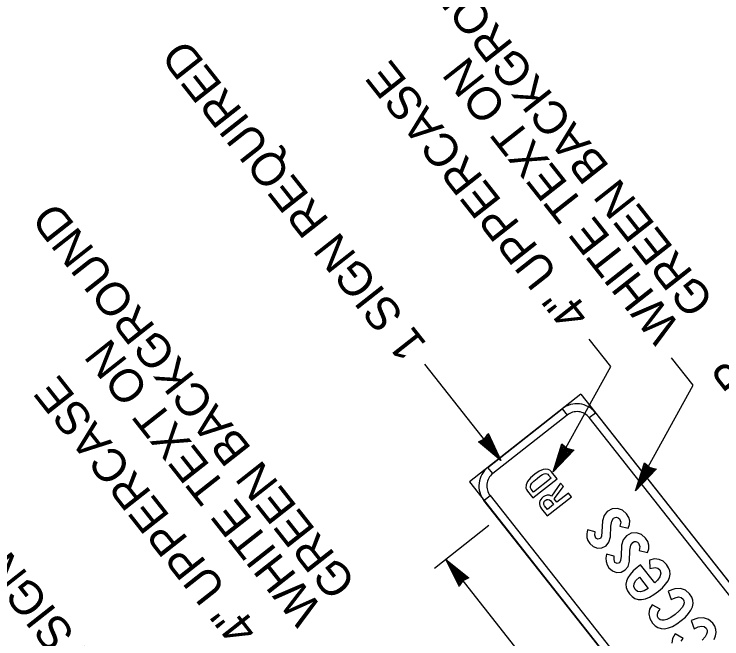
# Model space of a CAD drawing. Extents: x 672126 to 673696, y 1673540 to 1674900.
# Drawn here: x 672217.5 to 672307.3, y 1674682.5 to 1674761.8 of the extents above; entities that cross this region are included whole.
import ezdxf

# ---------------------------------------------------------------- set-up
doc = ezdxf.new("R2010")
doc.units = 0
doc.layers.add('C-ANNO-SYMB', color=7, linetype='Continuous')
doc.layers.add('Level 1', color=7, linetype='Continuous')

msp = doc.modelspace()

# ---------------------------------------------------------------- linework, layer by layer
at = {"layer": 'C-ANNO-SYMB'}
for p, q in [((672289.398, 1674713.6), (672275.262, 1674702.456)), ((672289.398, 1674713.6), (672333.973, 1674657.057)), ((672287.042, 1674711.743), (672287.661, 1674710.957)), ((672290.47, 1674710.625), (672291.255, 1674711.244)), ((672278.237, 1674703.528), (672277.618, 1674704.313)), ((672275.262, 1674702.456), (672319.838, 1674645.914)), ((672277.12, 1674700.1), (672277.905, 1674700.719))]:
    msp.add_line(p, q, dxfattribs=at)
for points in [[(672287.661, 1674710.957), (672278.237, 1674703.528), (672277.618, 1674704.313), (672287.042, 1674711.743), (672287.661, 1674710.957), (672287.661, 1674710.957)], [(672331.331, 1674658.794), (672290.47, 1674710.625), (672291.255, 1674711.244), (672332.116, 1674659.413), (672331.331, 1674658.794), (672331.331, 1674658.794)], [(672277.905, 1674700.719), (672318.766, 1674648.889), (672317.98, 1674648.27), (672277.12, 1674700.1), (672277.905, 1674700.719), (672277.905, 1674700.719)], [(672295.431, 1674696.575), (672295.593, 1674697.048), (672295.606, 1674697.514), (672295.476, 1674697.968), (672295.198, 1674698.414), (672294.678, 1674698.876), (672294.042, 1674699.085), (672293.377, 1674699.029), (672292.757, 1674698.696), (672292.36, 1674698.206), (672292.139, 1674697.505), (672292.076, 1674696.133), (672292.026, 1674695.564), (672291.886, 1674695.279), (672291.582, 1674695.19), (672291.31, 1674695.33), (672291.186, 1674695.704), (672291.212, 1674696.119), (672290.23, 1674696.362), (672290.154, 1674695.877), (672290.178, 1674695.427), (672290.307, 1674695.014), (672290.535, 1674694.64), (672290.976, 1674694.25), (672291.518, 1674694.064), (672292.088, 1674694.098), (672292.604, 1674694.368), (672292.965, 1674694.826), (672293.15, 1674695.501), (672293.208, 1674696.867), (672293.324, 1674697.494), (672293.568, 1674697.867), (672293.747, 1674697.958), (672293.95, 1674697.972), (672294.148, 1674697.907), (672294.302, 1674697.769), (672294.475, 1674697.338), (672294.371, 1674696.829)], [(672297.858, 1674693.496), (672298.02, 1674693.97), (672298.033, 1674694.435), (672297.903, 1674694.89), (672297.625, 1674695.336), (672297.105, 1674695.798), (672296.469, 1674696.007), (672295.803, 1674695.951), (672295.184, 1674695.618), (672294.787, 1674695.128), (672294.565, 1674694.426), (672294.503, 1674693.055), (672294.453, 1674692.486), (672294.312, 1674692.201), (672294.009, 1674692.111), (672293.736, 1674692.252), (672293.613, 1674692.626), (672293.639, 1674693.04), (672292.657, 1674693.284), (672292.581, 1674692.798), (672292.605, 1674692.348), (672292.734, 1674691.935), (672292.962, 1674691.561), (672293.403, 1674691.172), (672293.945, 1674690.986), (672294.515, 1674691.02), (672295.031, 1674691.289), (672295.392, 1674691.748), (672295.576, 1674692.423), (672295.635, 1674693.788), (672295.75, 1674694.415), (672295.995, 1674694.788), (672296.174, 1674694.88), (672296.377, 1674694.893), (672296.575, 1674694.829), (672296.729, 1674694.691), (672296.902, 1674694.26), (672296.798, 1674693.75)], [(672300.88, 1674687.534), (672301.372, 1674687.769), (672301.782, 1674687.859), (672302.117, 1674687.799), (672302.374, 1674687.594), (672302.493, 1674687.369), (672302.507, 1674687.118), (672302.426, 1674686.833), (672302.241, 1674686.523), (672301.878, 1674686.083), (672301.382, 1674685.643), (672300.842, 1674685.269), (672300.323, 1674685.019), (672299.981, 1674684.918), (672299.688, 1674684.904), (672299.45, 1674684.977), (672299.26, 1674685.139), (672299.128, 1674685.397), (672299.115, 1674685.674), (672299.224, 1674685.975), (672299.449, 1674686.295), (672298.446, 1674686.868), (672298.133, 1674686.311), (672298.04, 1674685.714), (672298.165, 1674685.112), (672298.498, 1674684.538), (672298.829, 1674684.196), (672299.194, 1674683.966), (672299.597, 1674683.844), (672300.033, 1674683.83), (672300.509, 1674683.924), (672301.018, 1674684.126), (672301.564, 1674684.438), (672302.147, 1674684.857), (672302.669, 1674685.308), (672303.079, 1674685.751), (672303.381, 1674686.188), (672303.567, 1674686.616), (672303.646, 1674687.036), (672303.611, 1674687.449), (672303.466, 1674687.852), (672303.209, 1674688.252), (672302.684, 1674688.724), (672302.056, 1674688.935), (672301.323, 1674688.887), (672300.483, 1674688.583)]]:
    msp.add_lwpolyline(points, close=True, dxfattribs=at)
for points in [[(672286.401, 1674702.865), (672285.693, 1674703.762), (672285.493, 1674703.95), (672285.248, 1674704.057), (672284.962, 1674704.082), (672284.63, 1674704.027), (672284.113, 1674703.816), (672283.587, 1674703.467), (672283.029, 1674702.972), (672282.65, 1674702.509), (672282.452, 1674702.081), (672282.434, 1674701.687), (672282.509, 1674701.498), (672282.657, 1674701.278), (672283.32, 1674700.436), (672286.401, 1674702.865)], [(672285.623, 1674702.937), (672283.396, 1674701.181), (672283.111, 1674701.542), (672283.021, 1674701.712), (672283.006, 1674701.898), (672283.068, 1674702.098), (672283.204, 1674702.312), (672283.456, 1674702.577), (672283.86, 1674702.918), (672284.208, 1674703.193), (672284.524, 1674703.388), (672284.765, 1674703.49), (672284.93, 1674703.516), (672285.077, 1674703.495), (672285.209, 1674703.429), (672285.322, 1674703.319), (672285.623, 1674702.937)], [(672288.209, 1674700.571), (672287.828, 1674701.055), (672286.361, 1674699.898), (672286.037, 1674700.31), (672287.186, 1674701.869), (672286.837, 1674702.311), (672285.672, 1674700.666), (672285.413, 1674700.772), (672285.129, 1674700.784), (672284.867, 1674700.711), (672284.62, 1674700.562), (672284.445, 1674700.403), (672284.31, 1674700.232), (672284.216, 1674700.053), (672284.162, 1674699.863), (672284.151, 1674699.661), (672284.188, 1674699.46), (672284.271, 1674699.26), (672284.401, 1674699.065), (672285.128, 1674698.143), (672288.209, 1674700.571)], [(672285.955, 1674699.578), (672285.17, 1674698.959), (672284.814, 1674699.411), (672284.716, 1674699.591), (672284.696, 1674699.78), (672284.757, 1674699.961), (672284.898, 1674700.116), (672285.089, 1674700.227), (672285.266, 1674700.252), (672285.433, 1674700.192), (672285.587, 1674700.046), (672285.955, 1674699.578)], [(672298.783, 1674689.644), (672296.979, 1674691.932), (672296.555, 1674691.597), (672296.054, 1674691.16), (672295.657, 1674690.728), (672295.372, 1674690.302), (672295.192, 1674689.881), (672295.126, 1674689.464), (672295.165, 1674689.054), (672295.316, 1674688.649), (672295.57, 1674688.253), (672295.903, 1674687.912), (672296.27, 1674687.678), (672296.676, 1674687.554), (672297.113, 1674687.541), (672297.593, 1674687.636), (672298.105, 1674687.84), (672298.654, 1674688.153), (672299.24, 1674688.576), (672299.758, 1674689.024), (672300.166, 1674689.465), (672300.465, 1674689.899), (672300.649, 1674690.325), (672300.726, 1674690.744), (672300.689, 1674691.159), (672300.542, 1674691.567), (672300.282, 1674691.965), (672299.837, 1674692.394), (672299.326, 1674692.632), (672298.75, 1674692.68), (672298.104, 1674692.535), (672298.141, 1674691.455), (672298.815, 1674691.583), (672299.172, 1674691.511), (672299.437, 1674691.299), (672299.574, 1674690.896), (672299.418, 1674690.396), (672299.151, 1674690.012), (672298.783, 1674689.644)], [(672297.956, 1674688.953), (672297.439, 1674688.631), (672296.989, 1674688.503), (672296.608, 1674688.566), (672296.296, 1674688.822), (672296.128, 1674689.176), (672296.159, 1674689.556), (672296.395, 1674689.956), (672296.83, 1674690.381), (672297.956, 1674688.953)], [(672306.303, 1674682.481), (672306.489, 1674682.909), (672306.568, 1674683.329), (672306.533, 1674683.742), (672306.389, 1674684.145), (672306.131, 1674684.546), (672305.607, 1674685.017), (672304.979, 1674685.229), (672304.246, 1674685.18), (672303.405, 1674684.876), (672303.802, 1674683.828), (672304.294, 1674684.062), (672304.704, 1674684.153), (672305.039, 1674684.092), (672305.296, 1674683.887), (672305.415, 1674683.663), (672305.429, 1674683.411), (672305.348, 1674683.126), (672305.163, 1674682.816), (672304.8, 1674682.376)], [(672302.146, 1674682.268), (672302.371, 1674682.588), (672301.368, 1674683.161), (672301.055, 1674682.604), (672300.962, 1674682.007)]]:
    msp.add_lwpolyline(points, dxfattribs=at)
for centre, radius, start, end in [((672288.899, 1674709.387), 3, 38.2506, 128.25081), ((672288.899, 1674709.387), 2, 38.2506, 128.25081), ((672279.476, 1674701.957), 3, 128.25054, 218.25075), ((672279.476, 1674701.957), 2, 128.25054, 218.25075)]:
    msp.add_arc(centre, radius, start, end, dxfattribs=at)
at = {"layer": 'Level 1'}
for p, q in [((672279.27, 1674705.167), (672269.612, 1674717.418)), ((672277.131, 1674707.856), (672277.618, 1674708.517)), ((672277.493, 1674708.16), (672277.687, 1674708.47)), ((672277.618, 1674708.517), (672277.55, 1674708.299)), ((672277.55, 1674708.299), (672277.646, 1674708.305)), ((672277.639, 1674708.664), (672279.27, 1674705.167)), ((672277.646, 1674708.305), (672279.008, 1674705.433)), ((672277.687, 1674708.47), (672278.92, 1674705.595)), ((672276.411, 1674707.549), (672277.178, 1674707.925)), ((672279.27, 1674705.167), (672276.411, 1674707.549)), ((672276.559, 1674707.527), (672277.131, 1674707.856)), ((672279.039, 1674705.39), (672276.559, 1674707.527)), ((672276.727, 1674707.521), (672276.99, 1674707.654)), ((672278.771, 1674705.747), (672276.727, 1674707.521)), ((672276.858, 1674707.52), (672277.571, 1674708.186)), ((672278.554, 1674706.042), (672276.858, 1674707.52)), ((672276.99, 1674707.654), (672277.571, 1674708.186)), ((672276.993, 1674707.558), (672277.509, 1674708.008)), ((672278.676, 1674705.968), (672276.993, 1674707.558)), ((672277.403, 1674707.929), (672277.125, 1674707.559)), ((672277.125, 1674707.559), (672277.872, 1674707.037)), ((672277.136, 1674707.5), (672277.466, 1674707.846)), ((672278.223, 1674706.483), (672277.136, 1674707.5)), ((672277.178, 1674707.925), (672277.493, 1674708.16)), ((672277.262, 1674707.462), (672277.414, 1674707.74)), ((672277.962, 1674706.876), (672277.262, 1674707.462)), ((672277.34, 1674707.49), (672277.407, 1674707.571)), ((672277.674, 1674707.217), (672277.34, 1674707.49)), ((672277.407, 1674707.571), (672277.403, 1674707.929)), ((672277.414, 1674707.74), (672277.674, 1674707.217)), ((672277.466, 1674707.846), (672277.962, 1674706.876)), ((672277.509, 1674708.008), (672278.223, 1674706.483)), ((672277.571, 1674708.186), (672278.554, 1674706.042)), ((672277.571, 1674708.186), (672278.676, 1674705.968)), ((672277.872, 1674707.037), (672277.967, 1674706.782)), ((672285.899, 1674703.731), (672287.015, 1674707.281)), ((672288.553, 1674706.53), (672285.899, 1674703.731)), ((672286.017, 1674704.029), (672287.052, 1674707.135)), ((672288.185, 1674706.425), (672286.045, 1674704.074)), ((672288.353, 1674706.449), (672286.161, 1674704.218)), ((672286.245, 1674704.413), (672287.11, 1674706.977)), ((672286.413, 1674704.585), (672287.246, 1674706.745)), ((672288.046, 1674706.449), (672286.413, 1674704.585)), ((672286.436, 1674704.726), (672287.159, 1674706.855)), ((672288.046, 1674706.449), (672286.436, 1674704.726)), ((672286.718, 1674705.199), (672287.246, 1674706.591)), ((672287.857, 1674706.439), (672286.718, 1674705.199)), ((672286.982, 1674705.589), (672287.259, 1674706.46)), ((672287.692, 1674706.418), (672286.982, 1674705.589)), ((672287.015, 1674707.281), (672287.655, 1674706.713)), ((672287.052, 1674707.135), (672287.574, 1674706.731)), ((672287.296, 1674706.624), (672287.097, 1674705.734)), ((672287.11, 1674706.977), (672287.332, 1674706.784)), ((672287.159, 1674706.855), (672288.046, 1674706.449)), ((672287.574, 1674706.425), (672287.189, 1674705.986)), ((672287.246, 1674706.745), (672287.857, 1674706.439)), ((672287.246, 1674706.591), (672287.692, 1674706.418)), ((672287.259, 1674706.46), (672287.574, 1674706.425)), ((672287.744, 1674706.506), (672287.296, 1674706.624)), ((672287.332, 1674706.784), (672288.046, 1674706.449)), ((672287.415, 1674706.367), (672287.744, 1674706.506)), ((672287.574, 1674706.731), (672288.37, 1674706.531)), ((672287.655, 1674706.713), (672287.992, 1674706.511)), ((672287.992, 1674706.511), (672288.353, 1674706.449)), ((672288.142, 1674706.512), (672288.185, 1674706.425)), ((672286.897, 1674705.549), (672286.685, 1674705.094)), ((672287.097, 1674705.734), (672286.897, 1674705.549)), ((672287.189, 1674705.986), (672287.314, 1674706.399)), ((672287.314, 1674706.399), (672287.415, 1674706.367)), ((672286.227, 1674704.176), (672286.82, 1674704.861)), ((672286.82, 1674704.861), (672286.245, 1674704.413)), ((672286.685, 1674705.094), (672287.017, 1674705.445)), ((672296.348, 1674701.343), (672297.465, 1674704.893)), ((672296.466, 1674701.641), (672297.501, 1674704.748)), ((672297.465, 1674704.893), (672298.104, 1674704.326)), ((672297.501, 1674704.748), (672298.023, 1674704.343)), ((672299.003, 1674704.142), (672296.348, 1674701.343)), ((672298.634, 1674704.038), (672296.494, 1674701.686)), ((672298.802, 1674704.062), (672296.611, 1674701.83)), ((672296.694, 1674702.025), (672297.559, 1674704.59)), ((672296.862, 1674702.197), (672297.695, 1674704.358)), ((672298.495, 1674704.061), (672296.862, 1674702.197)), ((672296.885, 1674702.338), (672297.608, 1674704.468)), ((672298.495, 1674704.061), (672296.885, 1674702.338)), ((672297.167, 1674702.811), (672297.695, 1674704.203)), ((672298.307, 1674704.052), (672297.167, 1674702.811)), ((672297.431, 1674703.202), (672297.708, 1674704.072)), ((672298.141, 1674704.03), (672297.431, 1674703.202)), ((672297.745, 1674704.236), (672297.546, 1674703.347)), ((672297.559, 1674704.59), (672297.782, 1674704.397)), ((672297.608, 1674704.468), (672298.495, 1674704.061)), ((672298.023, 1674704.037), (672297.638, 1674703.598)), ((672297.638, 1674703.598), (672297.764, 1674704.011)), ((672297.695, 1674704.358), (672298.307, 1674704.052)), ((672297.695, 1674704.203), (672298.141, 1674704.03)), ((672297.708, 1674704.072), (672298.023, 1674704.037)), ((672298.193, 1674704.119), (672297.745, 1674704.236)), ((672297.764, 1674704.011), (672297.864, 1674703.98)), ((672297.782, 1674704.397), (672298.495, 1674704.061)), ((672297.864, 1674703.98), (672298.193, 1674704.119)), ((672298.023, 1674704.343), (672298.819, 1674704.144)), ((672298.104, 1674704.326), (672298.441, 1674704.124)), ((672298.441, 1674704.124), (672298.802, 1674704.062)), ((672298.592, 1674704.124), (672298.634, 1674704.038)), ((672297.346, 1674703.162), (672297.135, 1674702.707)), ((672297.135, 1674702.707), (672297.466, 1674703.058)), ((672297.546, 1674703.347), (672297.346, 1674703.162)), ((672296.677, 1674701.788), (672297.269, 1674702.473)), ((672297.269, 1674702.473), (672296.694, 1674702.025)), ((672277.752, 1674696.92), (672270.848, 1674691.477)), ((672273.996, 1674689.154), (672272.292, 1674692.615)), ((672272.292, 1674692.615), (672275.201, 1674690.294)), ((672288.283, 1674672.401), (672272.326, 1674692.642)), ((672272.652, 1674692.195), (672272.528, 1674692.397)), ((672272.528, 1674692.397), (672275.052, 1674690.312)), ((672273.982, 1674689.512), (672272.56, 1674692.355)), ((672272.56, 1674692.355), (672272.589, 1674692.148)), ((672272.589, 1674692.148), (672273.014, 1674691.349)), ((672273.943, 1674689.346), (672272.652, 1674692.195)), ((672273.014, 1674691.349), (672272.804, 1674692.046)), ((672272.804, 1674692.046), (672274.884, 1674690.315)), ((672274.054, 1674689.633), (672272.903, 1674691.827)), ((672272.903, 1674691.827), (672274.619, 1674690.272)), ((672274.054, 1674689.633), (672273.027, 1674691.756)), ((672273.027, 1674691.756), (672274.752, 1674690.313)), ((672273.628, 1674691.028), (672273.281, 1674691.39)), ((672273.281, 1674691.39), (672273.488, 1674690.954)), ((672274.113, 1674689.812), (672273.366, 1674691.322)), ((672273.366, 1674691.322), (672274.474, 1674690.327)), ((672273.729, 1674690.775), (672273.628, 1674691.028)), ((672274.152, 1674689.974), (672273.635, 1674690.934)), ((672273.635, 1674690.934), (672274.347, 1674690.363)), ((672274.487, 1674690.269), (672273.729, 1674690.775)), ((672274.201, 1674690.082), (672273.931, 1674690.599)), ((672273.931, 1674690.599), (672274.27, 1674690.333)), ((672274.752, 1674690.313), (672274.054, 1674689.633)), ((672274.619, 1674690.272), (672274.113, 1674689.812)), ((672274.474, 1674690.327), (672274.152, 1674689.974)), ((672274.347, 1674690.363), (672274.201, 1674690.082)), ((672274.27, 1674690.333), (672274.205, 1674690.251)), ((672274.205, 1674690.251), (672274.216, 1674689.893)), ((672274.216, 1674689.893), (672274.487, 1674690.269)), ((672275.201, 1674690.294), (672274.441, 1674689.902)), ((672275.052, 1674690.312), (672274.487, 1674689.971)), ((672274.884, 1674690.315), (672274.624, 1674690.177)), ((672274.131, 1674689.66), (672273.943, 1674689.346)), ((672274.077, 1674689.52), (672273.982, 1674689.512)), ((672274.487, 1674689.971), (672274.014, 1674689.301)), ((672274.624, 1674690.177), (672274.054, 1674689.633)), ((672274.441, 1674689.902), (672274.131, 1674689.66))]:
    msp.add_line(p, q, dxfattribs=at)
for points in [[(672287.037, 1674705.938), (672293.199, 1674717.115), (672290.453, 1674720.598)], [(672297.486, 1674703.551), (672303.648, 1674714.727), (672300.902, 1674718.21)]]:
    msp.add_lwpolyline(points, dxfattribs=at)

# ---------------------------------------------------------------- texts
for s, p in [('GREEN BACKGROUND', (672306.475, 1674725.565)), ('1 SIGN REQUIRED', (672269.969, 1674719.957)), ('4" UPPERCASE', (672290.765, 1674723.805)), ('WHITE TEXT ON', (672302.181, 1674722.179)), ('GREEN BACKGROUND', (672261.061, 1674689.762)), ('2 SIGNS REQUIRED', (672228.252, 1674679.465)), ('WHITE TEXT ON', (672256.767, 1674686.377)), ('BORDER STRIP', (672335.04, 1674686.059)), ('4" UPPERCASE', (672248.676, 1674683.786))]:
    msp.add_text(s, height=4.2, rotation=128.25054, dxfattribs=at).set_placement(p)

doc.saveas('drawing.dxf')
